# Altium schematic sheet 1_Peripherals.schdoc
size 309 x 223 mm; Symbol: Sheet-Symbol_A4; Device: Sheet-Symbol_A4; @Project Name: Actuator Module; @Page Count: 6; @Update Date: 2025-01-18; @Create Date: 2024-10-16; @Schematic Name: Schematic-A_2; @Page No: 1; @Page Name: Peripherals; Company: UA Nasa Robotics; Reviewed: None; Version: 1.0; Page Size: A4; Part Number: AA; Drawn: Eli B; @Board Name: BaseModule; @Create Time: 17:38:13; @Update Time: 18:53:58
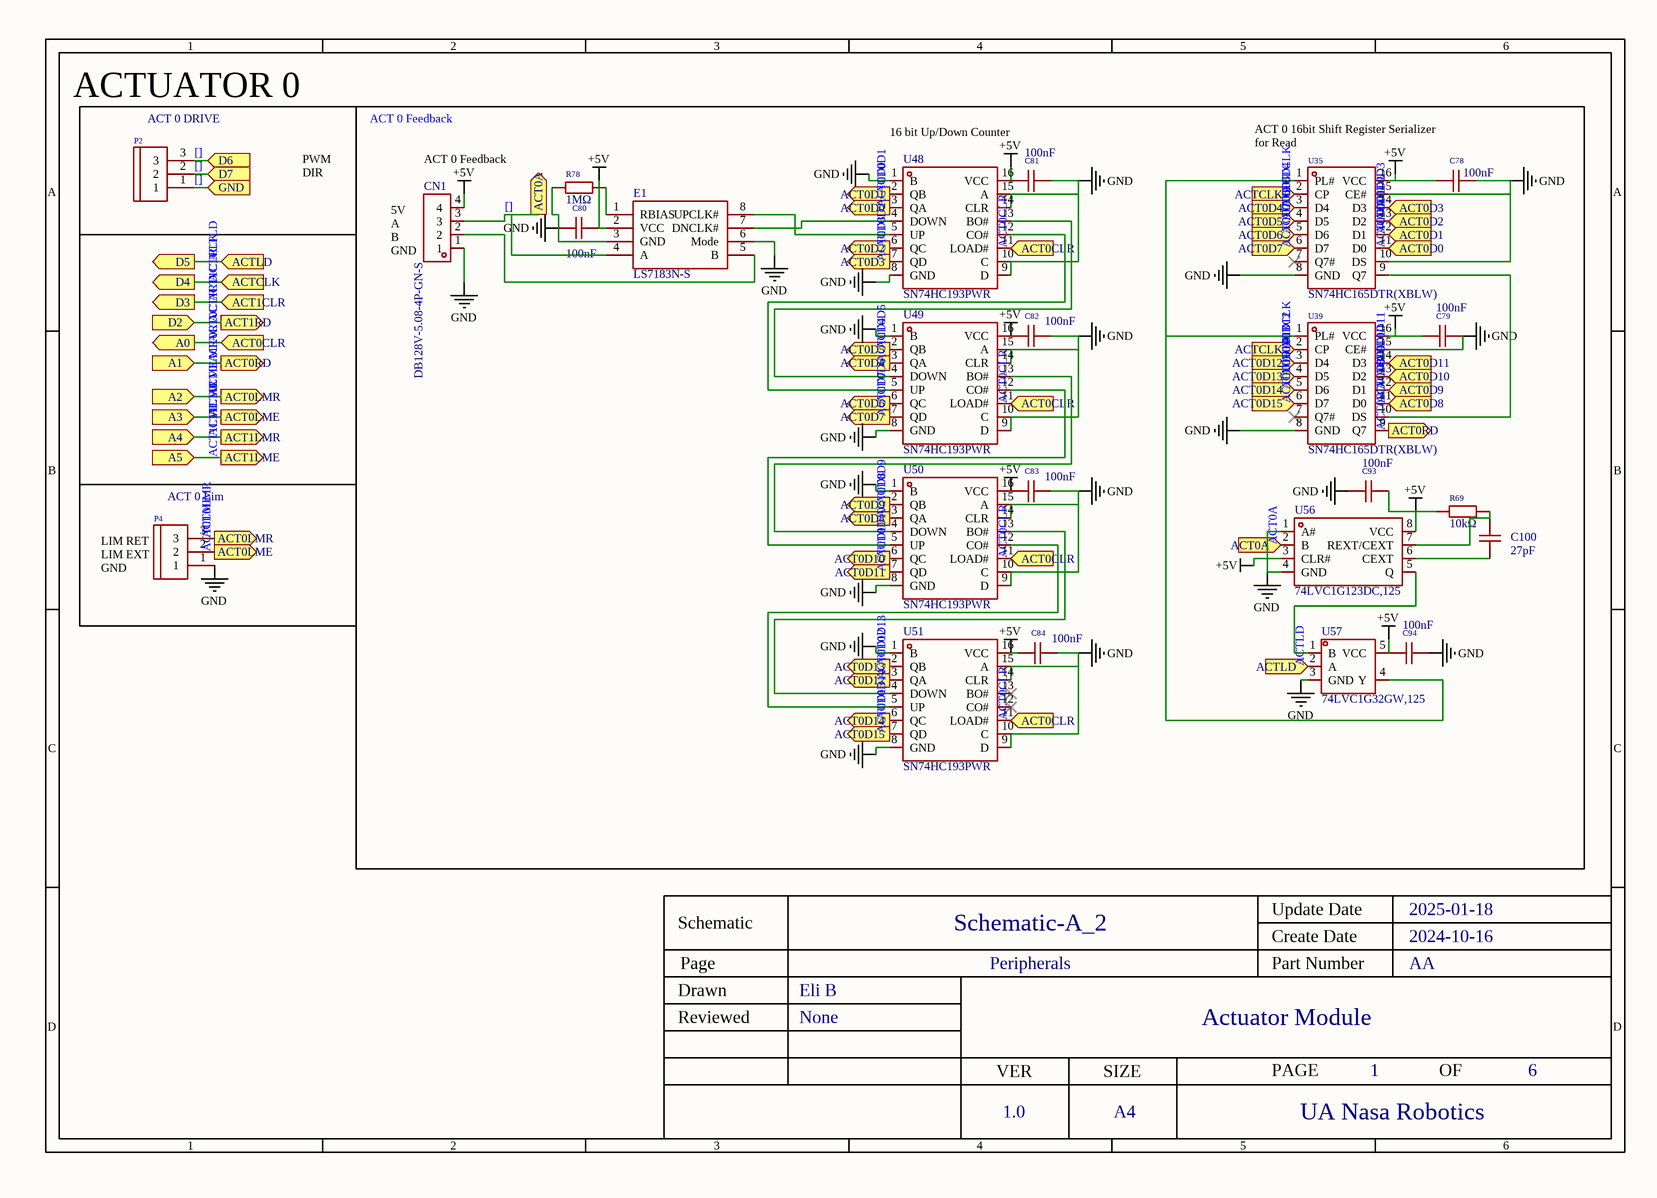
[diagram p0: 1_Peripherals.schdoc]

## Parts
C78  100nF  [C0805]
C79  100nF  [C0805]
C80  100nF  [C0805]
C81  100nF  [C0805]
C82  100nF  [C0805]
C83  100nF  [C0805]
C84  100nF  [C0805]
C93  100nF  [C0805]
C94  100nF  [C0805]
C100  27pF  [C0603]
CN1  DB128V-5.08-4P-GN-S  [CONN-TH_4P-P5.08_DIBO_DB128V-5.08]
E1  LS7183N-S  [SOIC-8_L5.0-W4.0-P1.27-LS6.0-TL]
P2  ACT 0 DRIVE  [CONN-TH_3P-P5.00_WJ500V-5.08-3P]
P4  ACT 0 Lim  [CONN-TH_3P-P5.00_WJ500V-5.08-3P]
R69  10kΩ  [R0805]
R78  1MΩ  [R1206]
U35  SN74HC165DTR(XBLW)  [SOP-16_L9.9-W3.9-P1.27-LS6.0-BL]
U39  SN74HC165DTR(XBLW)  [SOP-16_L9.9-W3.9-P1.27-LS6.0-BL]
U48  SN74HC193PWR  [TSSOP-16_L5.0-W4.4-P0.65-LS6.4-BL]
U49  SN74HC193PWR  [TSSOP-16_L5.0-W4.4-P0.65-LS6.4-BL]
U50  SN74HC193PWR  [TSSOP-16_L5.0-W4.4-P0.65-LS6.4-BL]
U51  SN74HC193PWR  [TSSOP-16_L5.0-W4.4-P0.65-LS6.4-BL]
U56  74LVC1G123DC,125  [VSSOP-8_L2.4-W2.1-P0.50-LS3.2-BR]
U57  74LVC1G32GW,125  [SOT-353_L2.2-W1.4-P0.65-LS2.4-BR]

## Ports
A0 (out), A1 (in), A2 (in), A3 (in), A4 (in), A5 (in), ACT0A (in), ACT0A (out), ACT0CLR (in), ACT0D0 (in), ACT0D0 (out), ACT0D1 (in), ACT0D1 (out), ACT0D2 (in), ACT0D2 (out), ACT0D3 (in), ACT0D3 (out), ACT0D4 (in), ACT0D4 (out), ACT0D5 (in), ACT0D5 (out), ACT0D6 (in), ACT0D6 (out), ACT0D7 (in), ACT0D7 (out), ACT0D8 (in), ACT0D8 (out), ACT0D9 (in), ACT0D9 (out), ACT0D10 (in), ACT0D10 (out), ACT0D11 (in), ACT0D11 (out), ACT0D12 (in), ACT0D12 (out), ACT0D13 (in), ACT0D13 (out), ACT0D14 (in), ACT0D14 (out), ACT0D15 (in), ACT0D15 (out), ACT0LME (out), ACT0LMR (out), ACT0RD (out), ACT1CLR (in), ACT1LME (out), ACT1LMR (out), ACT1RD (out), ACTCLK (in), ACTLD (in), D2 (in), D3 (out), D4 (out), D5 (out), D6 (in), D7 (in), GND (in)

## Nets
+5V: C78.1 C79.2 C80.2 C81.1 C82.1 C83.1 C84.1 C93.1 C94.2 CN1.4 E1.2(VCC) R69.1 U35.16(VCC) U39.16(VCC) U48.16(VCC) U49.16(VCC) U50.16(VCC) U51.16(VCC) U56.3(CLR#) U56.8(VCC) U57.5(VCC)
GND: C78.2 C79.1 C80.1 C81.2 C82.2 C83.2 C84.2 C93.2 C94.1 CN1.1 E1.3(GND) E1.6(Mode) P4.1 R78.1 U35.8(GND) U35.10(DS) U35.15(CE#) U39.8(GND) U39.15(CE#) U48.1(B) U48.8(GND) U48.9(D) U48.10(C) U48.14(CLR) U48.15(A) U49.1(B) U49.8(GND) U49.9(D) U49.10(C) U49.14(CLR) U49.15(A) U50.1(B) U50.8(GND) U50.9(D) U50.10(C) U50.14(CLR) U50.15(A) U51.1(B) U51.8(GND) U51.9(D) U51.10(C) U51.14(CLR) U51.15(A) U56.1(A#) U56.4(GND) U57.3(GND)
[]: CN1.3 E1.4(A) P2.1 P2.2 P2.3 U56.2(B) ; port D6, port D7, port GND, port ACT0A  [also labelled ACT0A]
ACT0CLR: U48.11(LOAD#) U49.11(LOAD#) U50.11(LOAD#) U51.11(LOAD#) ; port ACT0CLR, port A0
ACT0D0: U35.11(D0) U48.3(QA) ; port ACT0D0
ACT0D1: U35.12(D1) U48.2(QB) ; port ACT0D1
ACT0D2: U35.13(D2) U48.6(QC) ; port ACT0D2
ACT0D3: U35.14(D3) U48.7(QD) ; port ACT0D3
ACT0D4: U35.3(D4) U49.3(QA) ; port ACT0D4
ACT0D5: U35.4(D5) U49.2(QB) ; port ACT0D5
ACT0D6: U35.5(D6) U49.6(QC) ; port ACT0D6
ACT0D7: U35.6(D7) U49.7(QD) ; port ACT0D7
ACT0D8: U39.11(D0) U50.3(QA) ; port ACT0D8
ACT0D9: U39.12(D1) U50.2(QB) ; port ACT0D9
ACT0D10: U39.13(D2) U50.6(QC) ; port ACT0D10
ACT0D11: U39.14(D3) U50.7(QD) ; port ACT0D11
ACT0D12: U39.3(D4) U51.3(QA) ; port ACT0D12
ACT0D13: U39.4(D5) U51.2(QB) ; port ACT0D13
ACT0D14: U39.5(D6) U51.6(QC) ; port ACT0D14
ACT0D15: U39.6(D7) U51.7(QD) ; port ACT0D15
ACT0LME: P4.2 ; port ACT0LME, port A3
ACT0LMR: P4.3 ; port ACT0LMR, port A2
ACT0RD: U39.9(Q7) ; port ACT0RD, port A1
ACT1CLR: port ACT1CLR, port D3
ACT1LME: port ACT1LME, port A5
ACT1LMR: port ACT1LMR, port A4
ACT1RD: port ACT1RD, port D2
ACTCLK: U35.2(CP) U39.2(CP) ; port ACTCLK, port D4
ACTLD: U57.2(A) ; port ACTLD, port D5
NetC100_1: C100.1 U56.6(CEXT)
NetC100_2: C100.2 R69.2 U56.7(REXT/CEXT)
NetCN1_2: CN1.2 E1.5(B)
NetE1_1: E1.1(RBIAS) R78.2
NetE1_7: E1.7(DNCLK#) U48.4(DOWN)
NetE1_8: E1.8(UPCLK#) U48.5(UP)
NetU35_1: U35.1(PL#) U39.1(PL#) U57.4(Y)
NetU35_9: U35.9(Q7) U39.10(DS)
NetU48_12: U48.12(CO#) U49.5(UP)
NetU48_13: U48.13(BO#) U49.4(DOWN)
NetU49_12: U49.12(CO#) U50.5(UP)
NetU49_13: U49.13(BO#) U50.4(DOWN)
NetU50_12: U50.12(CO#) U51.5(UP)
NetU50_13: U50.13(BO#) U51.4(DOWN)
NetU56_5: U56.5(Q) U57.1(B)

Not connected (* = marked no-connect by the designer): U35 7(Q7#)*; U39 7(Q7#)*; U51 12(CO#)* 13(BO#)*

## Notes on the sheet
- ACTUATOR 0
- ACT 0 Feedback
- 16 bit Up/Down Counter
- (near U35) ACT 0 16bit Shift Register Serializer
  for Read
- PWM
- DIR
- (near CN1) 5V
  A
  B
  GND
- (near P4) LIM RET
  LIM EXT
  GND

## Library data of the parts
C78-C84 C93 C94 = 0805B104K500NT: Manufacturer: FH(风华); Add into BOM: yes; Tolerance: ±10%
C100 = CC0603JRNPO9BN270: Manufacturer: YAGEO(国巨); Add into BOM: yes; Tolerance: ±5%
CN1 = DB128V-5.08-4P-GN-S: Manufacturer: DORABO(地博电气); Add into BOM: yes; Structure: 1x4P; Pitch: 5.08mm; Current Rating (Max): 20A; Voltage Rating (Max): 300V; Wire Gauge - AWG: 12~30; Wire Gauge - mm2: 2.5; Number of PINs Per Row: 4
E1 = LS7183N-S: Add into BOM: yes
P2 P4 = WJ500V-5.08-3P: Manufacturer: KANGNEX(康奈克斯电气); Symbol: WJ500V-5.08-3P-14-00A; Add into BOM: yes; Structure: 1x3P; Pitch: 5.08mm; Current Rating (Max): 18A; Voltage Rating (Max): 250V; Wire Gauge - AWG: 14~30; Wire Gauge - mm2: 2.5; Number of PINs Per Row: 3
R69 = 0805W8F1002T5E: Manufacturer: UNI-ROYAL(厚声); Add into BOM: yes; Tolerance: ±1%; Temperature Coefficient: ±100ppm/℃
R78 = 1206W4F1004T5E: Manufacturer: UNI-ROYAL(厚声); Add into BOM: yes; Tolerance: ±1%; Temperature Coefficient: ±100ppm/℃
U35 U39 = SN74HC165DTR(XBLW): Manufacturer: XBLW(芯伯乐); Add into BOM: yes; Supply Voltage: 2V~6V
U48-U51 = SN74HC193PWR: Manufacturer: TI(德州仪器); Add into BOM: yes; Logic Type: Binary Counter; Direction: 向上计数器；向下计数器; Supply Voltage: 2V~6V; Number of Elements: 1; Number of Bits per Element: 4; Trigger Type: Positive Edge; Reset Style: 异步; Timing mode: Synchronous; Count Rate: 24MHz
U56 = 74LVC1G123DC,125: Manufacturer: Nexperia(安世); Add into BOM: yes; Logic Gate Type: Monostable; Supply Voltage: 1.65V~5.5V; Number Of Channels: 1; Input Type: Schmitt Trigger; Propagation Delay: 5.3ns; Sink Current: 32mA; Logic Family: 74LVC
U57 = 74LVC1G32GW,125: Manufacturer: Nexperia(安世); Add into BOM: yes; Logic Gate Type: ORGate; Number of Channels: 1; Supply Voltage: 1.65V~5.5V; Quiescent Current (Max): 4uA; Sink Current: 32mA; High Level Range (VIH): 1.7V~2V; Low Level Range (VIL): 700mV~800mV; Propagation Delay Time: 4ns@5V,50pF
